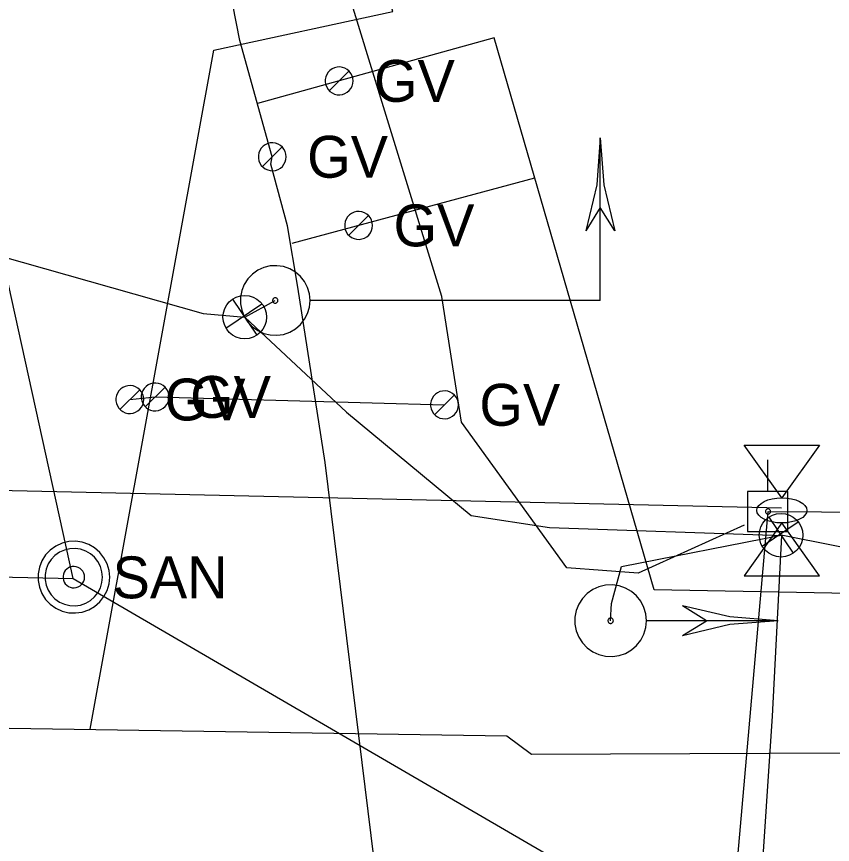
# Model space of a CAD drawing. Extents: x 596028 to 606371, y 330010 to 403088.
# Drawn here: x 605086 to 605161, y 349944.2 to 350020.4 of the extents above; entities that cross this region are included whole.
import ezdxf

# ---------------------------------------------------------------- set-up
doc = ezdxf.new("R2010")
doc.units = 0
for name, color, linetype in [('E_SIG', 7, 'Continuous'), ('E_SIG_Conduit', 7, 'Continuous'), ('E_UTL_E_Bold', 7, 'Continuous'), ('E_UTL_EPowerPole', 7, 'Continuous'), ('E_UTL_G', 7, 'Continuous'), ('E_UTL_G_UG', 7, 'Continuous'), ('E_UTL_Overhead', 7, 'Continuous'), ('E_UTL_SAN_MH', 7, 'Continuous'), ('E_UTL_SAN_UG', 7, 'Continuous'), ('E_UTL_TV_UG', 7, 'Continuous')]:
    doc.layers.add(name, color=color, linetype=linetype)

# ---------------------------------------------------------------- blocks, each defined once
blk = doc.blocks.new('_U335')
at = {"layer": 'E_SIG'}
for p, q in [((0, 6.1), (0, -6.1)), ((-6.09, 0.4), (6.1, 0.4))]:
    blk.add_line(p, q, dxfattribs=at)
blk.add_circle((0, 0.01), 6.1, dxfattribs=at)
blk = doc.blocks.new('_U354')
at = {"layer": 'E_SIG'}
for p, q in [((0, 6.1), (0, -6.1)), ((-6.09, 0.4), (6.1, 0.4))]:
    blk.add_line(p, q, dxfattribs=at)
blk.add_circle((0, 0.01), 6.1, dxfattribs=at)

msp = doc.modelspace()

# ---------------------------------------------------------------- linework, layer by layer
at = {"layer": 'E_SIG'}
for points in [[(605139.686, 350009.203), (605139.351, 350004.88), (605138.352, 350000.661)], [(605139.686, 350009.203), (605140.022, 350004.88), (605141.021, 350000.661)], [(605139.686, 349994.257), (605139.686, 350009.202)], [(605139.686, 350002.798), (605138.35, 350000.662)], [(605141.024, 350000.662), (605139.686, 350002.798)], [(605112.995, 349994.255), (605112.937, 349994.862), (605112.766, 349995.446), (605112.487, 349995.987), (605112.11, 349996.466), (605111.65, 349996.865), (605111.123, 349997.169), (605110.548, 349997.368), (605109.945, 349997.455), (605109.337, 349997.426), (605108.745, 349997.282), (605108.191, 349997.029), (605107.695, 349996.676), (605107.275, 349996.235), (605106.945, 349995.723), (605106.719, 349995.158), (605106.604, 349994.56), (605106.604, 349993.951), (605106.719, 349993.353), (605106.945, 349992.788), (605107.275, 349992.276), (605107.695, 349991.835), (605108.191, 349991.482), (605108.745, 349991.229), (605109.337, 349991.085), (605109.945, 349991.056), (605110.548, 349991.143), (605111.123, 349991.342), (605111.65, 349991.646), (605112.11, 349992.045), (605112.487, 349992.524), (605112.766, 349993.065), (605112.937, 349993.649), (605112.995, 349994.255)], [(605110.037, 349994.255), (605110.033, 349994.302), (605110.02, 349994.347), (605109.998, 349994.388), (605109.97, 349994.425), (605109.934, 349994.455), (605109.894, 349994.478), (605109.85, 349994.494), (605109.804, 349994.5), (605109.758, 349994.498), (605109.712, 349994.487), (605109.67, 349994.468), (605109.632, 349994.441), (605109.6, 349994.407), (605109.575, 349994.368), (605109.557, 349994.324), (605109.549, 349994.279), (605109.549, 349994.232), (605109.557, 349994.186), (605109.575, 349994.143), (605109.6, 349994.104), (605109.632, 349994.07), (605109.67, 349994.043), (605109.712, 349994.024), (605109.758, 349994.013), (605109.804, 349994.011), (605109.85, 349994.017), (605109.894, 349994.033), (605109.934, 349994.056), (605109.97, 349994.086), (605109.998, 349994.123), (605110.02, 349994.164), (605110.033, 349994.209), (605110.037, 349994.255)], [(605139.686, 349994.257), (605113.048, 349994.257)], [(605132.213, 349994.257), (605132.213, 349994.257)], [(605143.935, 349964.812), (605143.875, 349965.436), (605143.698, 349966.038), (605143.411, 349966.596), (605143.023, 349967.089), (605142.549, 349967.5), (605142.005, 349967.813), (605141.413, 349968.019), (605140.792, 349968.108), (605140.165, 349968.078), (605139.555, 349967.93), (605138.985, 349967.669), (605138.473, 349967.306), (605138.041, 349966.851), (605137.701, 349966.324), (605137.468, 349965.741), (605137.349, 349965.125), (605137.349, 349964.498), (605137.468, 349963.882), (605137.701, 349963.299), (605138.041, 349962.772), (605138.473, 349962.318), (605138.985, 349961.954), (605139.555, 349961.693), (605140.165, 349961.545), (605140.792, 349961.515), (605141.413, 349961.605), (605142.005, 349961.81), (605142.549, 349962.123), (605143.023, 349962.534), (605143.411, 349963.027), (605143.698, 349963.585), (605143.875, 349964.187), (605143.935, 349964.812)], [(605156.035, 349964.812), (605151.581, 349965.157), (605147.235, 349966.187)], [(605149.435, 349964.81), (605147.235, 349966.187)], [(605140.887, 349964.812), (605140.882, 349964.859), (605140.869, 349964.905), (605140.847, 349964.948), (605140.817, 349964.986), (605140.781, 349965.017), (605140.739, 349965.041), (605140.694, 349965.057), (605140.647, 349965.064), (605140.599, 349965.061), (605140.552, 349965.05), (605140.508, 349965.03), (605140.469, 349965.002), (605140.436, 349964.968), (605140.41, 349964.927), (605140.392, 349964.883), (605140.383, 349964.836), (605140.383, 349964.788), (605140.392, 349964.74), (605140.41, 349964.696), (605140.436, 349964.656), (605140.469, 349964.621), (605140.508, 349964.593), (605140.552, 349964.573), (605140.599, 349964.562), (605140.647, 349964.559), (605140.694, 349964.566), (605140.739, 349964.582), (605140.781, 349964.606), (605140.817, 349964.637), (605140.847, 349964.675), (605140.869, 349964.718), (605140.882, 349964.764), (605140.887, 349964.812)], [(605156.034, 349964.81), (605143.993, 349964.81)], [(605156.035, 349964.812), (605151.581, 349964.466), (605147.235, 349963.436)], [(605147.235, 349963.439), (605149.435, 349964.81)]]:
    msp.add_lwpolyline(points, dxfattribs=at)
at = {"layer": 'E_SIG_Conduit'}
for points in [[(604992.918, 349997.12), (605041.258, 350003.168), (605045.681, 350004), (605067.591, 350003.139), (605103.155, 349993.057), (605106.987, 349992.725)], [(605106.987, 349992.725), (605109.792, 349994.255)], [(605106.987, 349992.725), (605107.982, 349991.805), (605116.344, 349983.973), (605127.804, 349974.473), (605135, 349973.398), (605156.383, 349972.652)], [(605136.251, 349822.64), (605150.503, 349858.544), (605150.935, 349861.685), (605151.129, 349863.737), (605152.205, 349906.289), (605155.527, 349956.04), (605156.383, 349972.652)], [(605140.634, 349964.812), (605140.719, 349966.391), (605141.626, 349969.784), (605156.304, 349972.668)], [(605179.555, 349961.417), (605176.221, 349968.723), (605156.304, 349972.668)]]:
    msp.add_lwpolyline(points, dxfattribs=at)
at = {"layer": 'E_UTL_E_Bold'}
for points in [[(605152.915, 349980.955), (605159.843, 349980.955)], [(605156.379, 349976.11), (605152.915, 349980.955)], [(605159.843, 349980.955), (605156.379, 349976.11)], [(605156.379, 349973.8), (605152.915, 349968.955)], [(605159.843, 349968.955), (605156.379, 349973.8)], [(605152.915, 349968.955), (605159.843, 349968.955)]]:
    msp.add_lwpolyline(points, dxfattribs=at)
msp.add_ellipse((605156.379, 349974.955), major_axis=(2.309, 0), ratio=0.5, dxfattribs=at)
at = {"layer": 'E_UTL_EPowerPole'}
for points in [[(605155.076, 349976.696), (605155.076, 349979.604)], [(605156.92, 349976.696), (605153.232, 349976.696)], [(605153.232, 349976.696), (605153.232, 349973.004)], [(605156.92, 349973.004), (605156.92, 349976.696)], [(605155.346, 349974.853), (605155.342, 349974.898), (605155.329, 349974.942), (605155.309, 349974.982), (605155.281, 349975.018), (605155.246, 349975.047), (605155.207, 349975.07), (605155.164, 349975.085), (605155.119, 349975.091), (605155.074, 349975.089), (605155.03, 349975.078), (605154.989, 349975.06), (605154.952, 349975.033), (605154.921, 349975), (605154.896, 349974.962), (605154.879, 349974.92), (605154.871, 349974.876), (605154.871, 349974.83), (605154.879, 349974.786), (605154.896, 349974.744), (605154.921, 349974.706), (605154.952, 349974.673), (605154.989, 349974.646), (605155.03, 349974.628), (605155.074, 349974.617), (605155.119, 349974.615), (605155.164, 349974.621), (605155.207, 349974.636), (605155.246, 349974.659), (605155.281, 349974.688), (605155.309, 349974.724), (605155.329, 349974.764), (605155.342, 349974.808), (605155.346, 349974.853)], [(605153.232, 349973.004), (605156.92, 349973.004)]]:
    msp.add_lwpolyline(points, dxfattribs=at)
at = {"layer": 'E_UTL_G'}
for points in [[(605116.949, 350014.444), (605116.926, 350014.687), (605116.857, 350014.921), (605116.745, 350015.138), (605116.595, 350015.33), (605116.41, 350015.489), (605116.199, 350015.611), (605115.968, 350015.691), (605115.727, 350015.726), (605115.483, 350015.714), (605115.246, 350015.657), (605115.024, 350015.555), (605114.825, 350015.414), (605114.657, 350015.237), (605114.525, 350015.032), (605114.434, 350014.806), (605114.388, 350014.566), (605114.388, 350014.322), (605114.434, 350014.082), (605114.525, 350013.856), (605114.657, 350013.651), (605114.825, 350013.474), (605115.024, 350013.333), (605115.246, 350013.231), (605115.483, 350013.174), (605115.727, 350013.162), (605115.968, 350013.197), (605116.199, 350013.277), (605116.41, 350013.399), (605116.595, 350013.558), (605116.745, 350013.75), (605116.857, 350013.967), (605116.926, 350014.201), (605116.949, 350014.444)], [(605114.758, 350013.537), (605116.573, 350015.351)], [(605110.802, 350007.468), (605110.779, 350007.711), (605110.71, 350007.945), (605110.598, 350008.162), (605110.448, 350008.354), (605110.263, 350008.513), (605110.052, 350008.635), (605109.821, 350008.715), (605109.58, 350008.75), (605109.336, 350008.738), (605109.099, 350008.681), (605108.877, 350008.579), (605108.678, 350008.438), (605108.51, 350008.261), (605108.378, 350008.056), (605108.287, 350007.83), (605108.241, 350007.59), (605108.241, 350007.346), (605108.287, 350007.106), (605108.378, 350006.88), (605108.51, 350006.675), (605108.678, 350006.498), (605108.877, 350006.357), (605109.099, 350006.255), (605109.336, 350006.198), (605109.58, 350006.186), (605109.821, 350006.221), (605110.052, 350006.301), (605110.263, 350006.423), (605110.448, 350006.582), (605110.598, 350006.774), (605110.71, 350006.991), (605110.779, 350007.225), (605110.802, 350007.468)], [(605108.611, 350006.561), (605110.426, 350008.375)], [(605118.743, 350001.157), (605118.72, 350001.4), (605118.651, 350001.634), (605118.539, 350001.851), (605118.389, 350002.043), (605118.204, 350002.202), (605117.993, 350002.324), (605117.762, 350002.404), (605117.521, 350002.439), (605117.277, 350002.427), (605117.04, 350002.37), (605116.818, 350002.268), (605116.619, 350002.127), (605116.451, 350001.95), (605116.319, 350001.745), (605116.228, 350001.519), (605116.182, 350001.279), (605116.182, 350001.035), (605116.228, 350000.795), (605116.319, 350000.569), (605116.451, 350000.364), (605116.619, 350000.187), (605116.818, 350000.046), (605117.04, 349999.944), (605117.277, 349999.887), (605117.521, 349999.875), (605117.762, 349999.91), (605117.993, 349999.99), (605118.204, 350000.112), (605118.389, 350000.271), (605118.539, 350000.463), (605118.651, 350000.68), (605118.72, 350000.914), (605118.743, 350001.157)], [(605116.552, 350000.25), (605118.367, 350002.064)], [(605100.037, 349985.385), (605100.014, 349985.628), (605099.945, 349985.862), (605099.833, 349986.079), (605099.683, 349986.271), (605099.498, 349986.43), (605099.287, 349986.552), (605099.056, 349986.632), (605098.815, 349986.667), (605098.571, 349986.655), (605098.334, 349986.598), (605098.112, 349986.496), (605097.913, 349986.355), (605097.745, 349986.178), (605097.613, 349985.973), (605097.522, 349985.747), (605097.476, 349985.507), (605097.476, 349985.263), (605097.522, 349985.023), (605097.613, 349984.797), (605097.745, 349984.592), (605097.913, 349984.415), (605098.112, 349984.274), (605098.334, 349984.172), (605098.571, 349984.115), (605098.815, 349984.103), (605099.056, 349984.138), (605099.287, 349984.218), (605099.498, 349984.34), (605099.683, 349984.499), (605099.833, 349984.691), (605099.945, 349984.908), (605100.014, 349985.142), (605100.037, 349985.385)], [(605097.705, 349985.148), (605097.682, 349985.391), (605097.613, 349985.625), (605097.501, 349985.842), (605097.351, 349986.034), (605097.166, 349986.193), (605096.955, 349986.315), (605096.724, 349986.395), (605096.483, 349986.43), (605096.239, 349986.418), (605096.002, 349986.361), (605095.78, 349986.259), (605095.581, 349986.118), (605095.413, 349985.941), (605095.281, 349985.736), (605095.19, 349985.51), (605095.144, 349985.27), (605095.144, 349985.026), (605095.19, 349984.786), (605095.281, 349984.56), (605095.413, 349984.355), (605095.581, 349984.178), (605095.78, 349984.037), (605096.002, 349983.935), (605096.239, 349983.878), (605096.483, 349983.866), (605096.724, 349983.901), (605096.955, 349983.981), (605097.166, 349984.103), (605097.351, 349984.262), (605097.501, 349984.454), (605097.613, 349984.671), (605097.682, 349984.905), (605097.705, 349985.148)], [(605095.514, 349984.241), (605097.329, 349986.055)], [(605097.846, 349984.478), (605099.661, 349986.292)], [(605126.639, 349984.663), (605126.616, 349984.906), (605126.547, 349985.14), (605126.435, 349985.357), (605126.285, 349985.549), (605126.1, 349985.708), (605125.889, 349985.83), (605125.658, 349985.91), (605125.417, 349985.945), (605125.173, 349985.933), (605124.936, 349985.876), (605124.714, 349985.774), (605124.515, 349985.633), (605124.347, 349985.456), (605124.215, 349985.251), (605124.124, 349985.025), (605124.078, 349984.785), (605124.078, 349984.541), (605124.124, 349984.301), (605124.215, 349984.075), (605124.347, 349983.87), (605124.515, 349983.693), (605124.714, 349983.552), (605124.936, 349983.45), (605125.173, 349983.393), (605125.417, 349983.381), (605125.658, 349983.416), (605125.889, 349983.496), (605126.1, 349983.618), (605126.285, 349983.777), (605126.435, 349983.969), (605126.547, 349984.186), (605126.616, 349984.42), (605126.639, 349984.663)], [(605124.448, 349983.756), (605126.263, 349985.57)]]:
    msp.add_lwpolyline(points, dxfattribs=at)
at = {"layer": 'E_UTL_G_UG'}
for p, q in [((605129.934, 350018.414), (605108.159, 350012.355)), ((605111.35, 349999.512), (605133.671, 350005.522))]:
    msp.add_line(p, q, dxfattribs=at)
for points in [[(605114.391, 349979.351), (605111.866, 349995.487), (605110.919, 350001.115), (605109.392, 350006.786), (605109.519, 350007.468), (605106.542, 350018.168), (605100.012, 350051.442), (605094.141, 350083.047), (605091.346, 350096.49)], [(605092.763, 349954.838), (605104.151, 350017.259), (605120.607, 350020.816), (605119.625, 350024.285)], [(605174.049, 349952.919), (605174.049, 349967.101), (605144.646, 349967.661), (605129.934, 350018.414)], [(605096.422, 349985.148), (605098.754, 349985.385), (605125.356, 349984.663)], [(605122.711, 349691.861), (605135.038, 349706.704), (605143.619, 349720.074), (605142.416, 349734.302), (605141.577, 349746.736), (605140.161, 349761.273), (605138.912, 349774.495), (605136.949, 349797.485), (605134.93, 349816.475), (605132.498, 349848.408), (605126.902, 349882.7), (605123.425, 349906.067), (605114.391, 349979.351)], [(605133.355, 349952.542), (605191.579, 349952.78), (605191.579, 349960.548)], [(605008.038, 349952.519), (605013.649, 349956.039), (605131.083, 349954.233), (605133.355, 349952.542)]]:
    msp.add_lwpolyline(points, dxfattribs=at)
at = {"layer": 'E_UTL_Overhead'}
for points in [[(603181.282, 350035.1), (603329.315, 350032.131), (603487.194, 350051.843), (603697.501, 350053.105), (603794.729, 350045.636), (603986.796, 350030.716), (604135.55, 350019.102), (604355.797, 350001.358), (604456.041, 349993.241), (604557.107, 349986.135), (604654.488, 349982.639), (604747.334, 349981.141), (604855.959, 349980.055), (604969.764, 349979.401), (605156.332, 349975.184)], [(605143.813, 349749.735), (605141.525, 349819.921), (605155.108, 349974.853), (605253.264, 349974.254), (605333.848, 349972.876), (605354.106, 349970.796), (605513.442, 349968.286), (605659.829, 349966.499)]]:
    msp.add_lwpolyline(points, dxfattribs=at)
at = {"layer": 'E_UTL_SAN_MH'}
for points in [[(605094.569, 349968.819), (605094.51, 349969.444), (605094.333, 349970.046), (605094.046, 349970.603), (605093.658, 349971.096), (605093.184, 349971.507), (605092.64, 349971.821), (605092.047, 349972.026), (605091.427, 349972.115), (605090.8, 349972.086), (605090.19, 349971.938), (605089.619, 349971.677), (605089.108, 349971.313), (605088.676, 349970.859), (605088.336, 349970.331), (605088.103, 349969.749), (605087.984, 349969.133), (605087.984, 349968.506), (605088.103, 349967.889), (605088.336, 349967.307), (605088.676, 349966.779), (605089.108, 349966.325), (605089.619, 349965.961), (605090.19, 349965.701), (605090.8, 349965.553), (605091.427, 349965.523), (605092.047, 349965.612), (605092.64, 349965.817), (605093.184, 349966.131), (605093.658, 349966.542), (605094.046, 349967.035), (605094.333, 349967.593), (605094.51, 349968.195), (605094.569, 349968.819)], [(605093.909, 349968.819), (605093.862, 349969.319), (605093.72, 349969.8), (605093.49, 349970.246), (605093.18, 349970.641), (605092.801, 349970.97), (605092.366, 349971.221), (605091.892, 349971.385), (605091.395, 349971.456), (605090.894, 349971.432), (605090.406, 349971.314), (605089.949, 349971.106), (605089.541, 349970.814), (605089.194, 349970.451), (605088.923, 349970.029), (605088.736, 349969.563), (605088.641, 349969.07), (605088.641, 349968.568), (605088.736, 349968.075), (605088.923, 349967.609), (605089.194, 349967.187), (605089.541, 349966.824), (605089.949, 349966.533), (605090.406, 349966.324), (605090.894, 349966.206), (605091.395, 349966.182), (605091.892, 349966.254), (605092.366, 349966.418), (605092.801, 349966.669), (605093.18, 349966.997), (605093.49, 349967.392), (605093.72, 349967.838), (605093.862, 349968.32), (605093.909, 349968.819)], [(605092.259, 349968.819), (605092.242, 349969.007), (605092.189, 349969.187), (605092.102, 349969.354), (605091.986, 349969.502), (605091.844, 349969.626), (605091.681, 349969.72), (605091.503, 349969.781), (605091.317, 349969.808), (605091.129, 349969.799), (605090.946, 349969.755), (605090.774, 349969.677), (605090.621, 349969.567), (605090.491, 349969.431), (605090.39, 349969.273), (605090.32, 349969.098), (605090.284, 349968.913), (605090.284, 349968.725), (605090.32, 349968.54), (605090.39, 349968.366), (605090.491, 349968.207), (605090.621, 349968.071), (605090.774, 349967.962), (605090.946, 349967.884), (605091.129, 349967.839), (605091.317, 349967.83), (605091.503, 349967.857), (605091.681, 349967.919), (605091.844, 349968.013), (605091.986, 349968.136), (605092.102, 349968.284), (605092.189, 349968.451), (605092.242, 349968.632), (605092.259, 349968.819)]]:
    msp.add_lwpolyline(points, dxfattribs=at)
at = {"layer": 'E_UTL_SAN_UG'}
for p, q in [((605035.81, 349969.837), (605091.219, 349968.705)), ((605091.219, 349968.705), (605146.814, 349936.364))]:
    msp.add_line(p, q, dxfattribs=at)
msp.add_lwpolyline([(605091.219, 349968.705), (605057.941, 350119.842)], dxfattribs=at)
at = {"layer": 'E_UTL_TV_UG'}
msp.add_lwpolyline([(605152.913, 349973.613), (605143.16, 349969.17), (605136.617, 349969.682), (605126.921, 349983.061), (605125.103, 349994.627), (605106.358, 350055.637), (605102.247, 350084.082)], dxfattribs=at)

# ---------------------------------------------------------------- block references
at = {"layer": 'E_SIG_Conduit', "xscale": 0.32808333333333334, "yscale": 0.3280833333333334, "rotation": 34.193210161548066}
for name, p in [('_U354', (605106.989, 349992.723)), ('_U335', (605156.304, 349972.668))]:
    msp.add_blockref(name, p, dxfattribs=at)

# ---------------------------------------------------------------- texts
at = {"layer": 'E_UTL_G'}
for p in [(605118.874, 350012.519), (605112.727, 350005.543), (605120.668, 349999.232), (605101.962, 349983.46), (605099.63, 349983.223), (605128.564, 349982.738)]:
    msp.add_text('GV', height=3.85, dxfattribs=at).set_placement(p)
at = {"layer": 'E_UTL_SAN_MH'}
msp.add_text('SAN', height=3.8491, dxfattribs=at).set_placement((605094.833, 349966.874))

doc.saveas('drawing.dxf')
